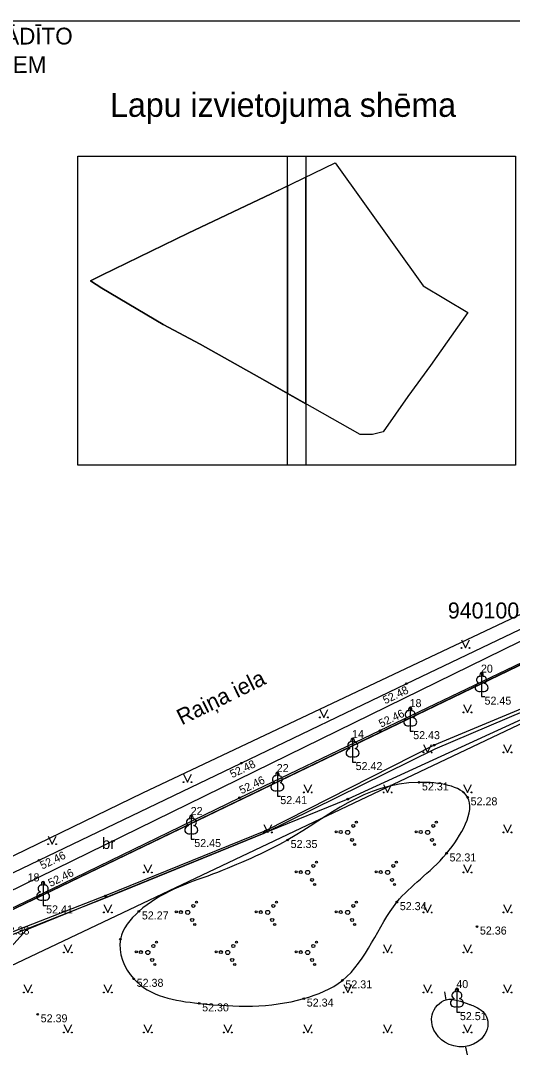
# Model space of a CAD drawing. Extents: x 619806 to 620082, y 405176 to 405386.
# Drawn here: x 619867.1 to 619897.8, y 405308.1 to 405373.2 of the extents above; entities that cross this region are included whole.
import ezdxf

# ---------------------------------------------------------------- set-up
doc = ezdxf.new("R2010")
doc.units = 0
for name, color, linetype in [('24', 7, 'Continuous'), ('APGR_SARK_####_####_#', 7, 'Continuous'), ('APGS_VADP_ZSPR_####_#', 7, 'Continuous'), ('CELI_CMAL_####_####_#', 7, 'Continuous'), ('CELI_CSEG_####_TKST_#', 7, 'Continuous'), ('CELI_IELA_####_TKST_#', 7, 'Continuous'), ('RAMI_PLAN_####_TKST_#', 7, 'Continuous'), ('RAMI_UZMR_####_####_#', 7, 'Continuous'), ('RELJ_AATZ_####_TKST_#', 7, 'Continuous'), ('RELJ_ELEM_####_####_#', 7, 'Continuous'), ('RELJ_HORZ_PAMT_####_#', 7, 'Continuous'), ('ROBZ_PROJ_####_TKST_#', 7, 'Continuous'), ('ROBZ_UZMR_####_####_#', 7, 'Continuous'), ('SAKT_VADP_KABE_####_#', 7, 'Continuous'), ('TERT_DIAM_####_TKST_#', 7, 'Continuous'), ('TERT_ELEM_####_####_#', 7, 'Continuous'), ('TERT_KONT_####_####_#', 7, 'Continuous')]:
    doc.layers.add(name, color=color, linetype=linetype)

msp = doc.modelspace()

# ---------------------------------------------------------------- linework, layer by layer
at = {"layer": '24'}
msp.add_line((619931.837, 405349.12), (619818.193, 405294.391), dxfattribs=at)
at = {"layer": 'APGR_SARK_####_####_#'}
msp.add_lwpolyline([(619818.56, 405291.467), (619964.609, 405360.731), (619976.198, 405343.424)], dxfattribs=at)
at = {"layer": 'APGS_VADP_ZSPR_####_#'}
for points in [[(619961.504, 405361.726), (619961.549, 405360.889), (619955.561, 405357.47), (619948.629, 405353.911), (619942.586, 405351.309), (619934.737, 405347.784), (619926.308, 405343.807), (619921.62, 405341.722), (619914.616, 405338.589), (619904.064, 405332.419), (619892.947, 405327.707), (619882.253, 405322.432), (619872.343, 405318.394), (619866.043, 405315.914), (619858.147, 405313.031), (619849.141, 405308.474), (619837.591, 405302.476), (619829.867, 405298.738), (619827.533, 405297.619), (619826.332, 405294.789), (619825.868, 405290.973), (619826.009, 405290.873), (619827.279, 405290.766)], [(619961.504, 405361.726), (619961.582, 405360.944), (619961.547, 405359.255), (619942.312, 405349.715), (619925.4, 405342.794), (619907.997, 405333.971), (619887.51, 405324.581), (619867.415, 405316.417), (619859.827, 405308.06), (619845.28, 405301.51), (619837.164, 405301.798), (619827.1, 405298.963), (619826.475, 405294.709), (619826.025, 405290.988), (619827.279, 405290.766)], [(619904.019, 405332.565), (619892.911, 405327.951), (619882.359, 405322.589), (619872.341, 405318.531), (619866.186, 405316.142), (619865.74, 405316.62), (619866.013, 405316.067), (619858.137, 405313.192), (619849.107, 405308.602), (619837.621, 405302.637), (619837.373, 405303.082), (619837.457, 405302.572), (619827.49, 405297.724), (619826.22, 405294.811), (619826.787, 405293.322), (619828.348, 405292.084), (619828.449, 405291.159), (619827.279, 405290.766)]]:
    msp.add_lwpolyline(points, dxfattribs=at)
at = {"layer": 'CELI_CMAL_####_####_#'}
for points in [[(619825.042, 405301.626), (619825.997, 405300.736), (619826.865, 405300.888), (619837.411, 405305.982), (619845.924, 405310.094), (619856.691, 405315.252), (619868.203, 405320.761), (619880.848, 405326.828), (619891.162, 405331.79), (619903.487, 405337.685), (619914.792, 405343.079), (619924.282, 405347.611), (619934.782, 405352.643), (619943.391, 405356.735), (619942.998, 405357.499)], [(619901.141, 405301.297), (619895.285, 405291.495), (619886.767, 405291.266), (619876.357, 405290.867), (619868.929, 405290.713), (619868.879, 405291.869), (619865.764, 405291.699), (619865.807, 405290.556), (619863.458, 405290.505), (619853.554, 405290.137), (619841.43, 405289.76), (619840.169, 405289.507), (619836.17, 405288.32), (619833.502, 405287.788), (619826.905, 405297.999), (619827.372, 405299.068), (619837.906, 405304.107), (619846.534, 405308.229), (619856.914, 405313.201), (619868.255, 405318.592), (619880.738, 405324.67), (619889.516, 405328.858), (619904.867, 405336.211)]]:
    msp.add_lwpolyline(points, dxfattribs=at)
at = {"layer": 'RAMI_PLAN_####_TKST_#'}
for p, q in [((619883.741, 405362.889), (619882.724, 405362.393)), ((619884.891, 405363.451), (619883.741, 405362.889)), ((619883.741, 405349.933), (619883.741, 405362.889)), ((619883.741, 405362.889), (619883.741, 405349.933)), ((619884.891, 405349.28), (619884.891, 405363.451)), ((619883.741, 405349.933), (619884.891, 405349.28))]:
    msp.add_line(p, q, dxfattribs=at)
for points in [[(619805.793, 405180.095), (619805.793, 405373.209), (619948.393, 405373.209), (619948.393, 405180.095)], [(619870.631, 405345.448), (619870.631, 405364.759), (619884.891, 405364.759), (619884.891, 405345.448)], [(619877.521, 405359.936), (619882.724, 405362.393), (619886.719, 405364.343), (619892.226, 405356.641), (619895.022, 405354.986), (619892.671, 405351.667), (619891.267, 405349.73), (619889.712, 405347.531), (619889.052, 405347.356), (619888.285, 405347.354), (619882.319, 405350.74), (619878.266, 405353.014), (619875.96, 405354.244), (619872.117, 405356.51), (619871.426, 405356.959), (619872.117, 405357.314)], [(619883.741, 405345.448), (619883.741, 405364.759), (619898.001, 405364.759), (619898.001, 405345.448)]]:
    msp.add_lwpolyline(points, close=True, dxfattribs=at)
msp.add_lwpolyline([(619882.724, 405362.393), (619877.521, 405359.936), (619872.117, 405357.314), (619871.426, 405356.959), (619872.117, 405356.51), (619875.96, 405354.244), (619878.266, 405353.014), (619882.319, 405350.74), (619883.741, 405349.933)], dxfattribs=at)
at = {"layer": 'RAMI_UZMR_####_####_#'}
msp.add_lwpolyline([(619874.687, 405324.979), (619926.719, 405349.544), (619966.669, 405369.042), (620021.738, 405292.03), (620049.703, 405275.476), (620026.189, 405242.287), (620012.147, 405222.917), (619996.603, 405200.928), (619989.997, 405199.173), (619982.328, 405199.155), (619922.669, 405233.014), (619882.137, 405255.756), (619859.084, 405268.056), (619820.646, 405290.715), (619813.744, 405295.206), (619820.645, 405298.752)], close=True, dxfattribs=at)
at = {"layer": 'RELJ_ELEM_####_####_#'}
for centre in [(619891.162, 405331.79), (619889.516, 405328.858), (619892.911, 405327.951), (619880.848, 405326.828), (619891.96, 405325.624), (619880.738, 405324.67), (619887.51, 405324.581), (619895.002, 405324.693), (619882.359, 405322.589), (619883.748, 405322.027), (619893.682, 405321.188), (619868.203, 405320.761), (619868.255, 405318.592), (619872.341, 405318.531), (619890.574, 405318.144), (619874.444, 405317.563), (619895.583, 405316.619), (619867.415, 405316.417), (619873.286, 405315.83), (619874.12, 405313.353), (619887.171, 405313.256), (619884.756, 405312.118), (619878.214, 405311.817), (619868.118, 405311.135)]:
    msp.add_circle(centre, 0.05, dxfattribs=at)
at = {"layer": 'RELJ_HORZ_PAMT_####_#'}
for p, q in [((619893.545, 405312.534), (619893.634, 405312.042)), ((619894.99, 405308.597), (619894.891, 405309.087))]:
    msp.add_line(p, q, dxfattribs=at)
msp.add_spline([(619895.163, 405311.743), (619895.492, 405311.611), (619896.23, 405310.859), (619895.861, 405309.606), (619893.569, 405309.395), (619892.779, 405311.096), (619893.662, 405312.046), (619895.081, 405311.766), (619895.161, 405311.743)], degree=3, dxfattribs=at)
at = {"layer": 'ROBZ_UZMR_####_####_#'}
msp.add_line((619818.193, 405294.391), (619931.837, 405349.12), dxfattribs=at)
at = {"layer": 'SAKT_VADP_KABE_####_#'}
msp.add_lwpolyline([(619816.151, 405294.73), (619838.42, 405305.23), (619866.149, 405318.697), (619899.278, 405334.929), (619937.202, 405353.635), (619962.924, 405366.289), (619964.424, 405369.208)], dxfattribs=at)
at = {"layer": 'TERT_ELEM_####_####_#'}
for p, q in [((619894.615, 405334.523), (619894.865, 405334.023)), ((619894.865, 405334.023), (619895.115, 405334.523)), ((619895.873, 405331.33), (619895.873, 405330.983)), ((619895.873, 405330.983), (619896.073, 405330.983)), ((619894.75, 405330.5), (619895, 405330)), ((619895, 405330), (619895.25, 405330.5)), ((619885.766, 405330.188), (619886.016, 405329.688)), ((619886.016, 405329.688), (619886.266, 405330.188)), ((619891.41, 405329.174), (619891.41, 405328.827)), ((619891.41, 405328.827), (619891.61, 405328.827)), ((619892.25, 405328), (619892.5, 405327.5)), ((619892.5, 405327.5), (619892.75, 405328)), ((619897.25, 405328), (619897.5, 405327.5)), ((619897.5, 405327.5), (619897.75, 405328)), ((619887.811, 405327.242), (619887.811, 405326.895)), ((619887.811, 405326.895), (619888.011, 405326.895)), ((619877.237, 405326.142), (619877.487, 405325.642)), ((619877.487, 405325.642), (619877.737, 405326.142)), ((619883.103, 405325.116), (619883.103, 405324.769)), ((619884.75, 405325.5), (619885, 405325)), ((619885, 405325), (619885.25, 405325.5)), ((619889.75, 405325.5), (619890, 405325)), ((619890, 405325), (619890.25, 405325.5)), ((619894.75, 405325.5), (619895, 405325)), ((619895, 405325), (619895.25, 405325.5)), ((619883.103, 405324.769), (619883.303, 405324.769)), ((619882.25, 405323), (619882.5, 405322.5)), ((619882.5, 405322.5), (619882.75, 405323)), ((619897.25, 405323), (619897.5, 405322.5)), ((619897.5, 405322.5), (619897.75, 405323)), ((619868.771, 405322.264), (619869.021, 405321.764)), ((619869.021, 405321.764), (619869.271, 405322.264)), ((619877.722, 405322.433), (619877.722, 405322.086)), ((619877.722, 405322.086), (619877.922, 405322.086)), ((619874.75, 405320.5), (619875, 405320)), ((619875, 405320), (619875.25, 405320.5)), ((619894.75, 405320.5), (619895, 405320)), ((619895, 405320), (619895.25, 405320.5)), ((619868.456, 405318.287), (619868.456, 405317.94)), ((619868.456, 405317.94), (619868.656, 405317.94)), ((619872.25, 405318), (619872.5, 405317.5)), ((619872.5, 405317.5), (619872.75, 405318)), ((619892.25, 405318), (619892.5, 405317.5)), ((619892.5, 405317.5), (619892.75, 405318)), ((619897.25, 405318), (619897.5, 405317.5)), ((619897.5, 405317.5), (619897.75, 405318)), ((619869.75, 405315.5), (619870, 405315)), ((619870, 405315), (619870.25, 405315.5)), ((619889.75, 405315.5), (619890, 405315)), ((619890, 405315), (619890.25, 405315.5)), ((619894.75, 405315.5), (619895, 405315)), ((619895, 405315), (619895.25, 405315.5)), ((619867.25, 405313), (619867.5, 405312.5)), ((619867.5, 405312.5), (619867.75, 405313)), ((619872.25, 405313), (619872.5, 405312.5)), ((619872.5, 405312.5), (619872.75, 405313)), ((619887.25, 405313), (619887.5, 405312.5)), ((619887.5, 405312.5), (619887.75, 405313)), ((619892.25, 405313), (619892.5, 405312.5)), ((619892.5, 405312.5), (619892.75, 405313)), ((619897.25, 405313), (619897.5, 405312.5)), ((619897.5, 405312.5), (619897.75, 405313)), ((619894.333, 405311.619), (619894.333, 405311.272)), ((619894.333, 405311.272), (619894.533, 405311.272)), ((619869.75, 405310.5), (619870, 405310)), ((619870, 405310), (619870.25, 405310.5)), ((619874.75, 405310.5), (619875, 405310)), ((619875, 405310), (619875.25, 405310.5)), ((619879.75, 405310.5), (619880, 405310)), ((619880, 405310), (619880.25, 405310.5)), ((619884.75, 405310.5), (619885, 405310)), ((619885, 405310), (619885.25, 405310.5)), ((619889.75, 405310.5), (619890, 405310)), ((619890, 405310), (619890.25, 405310.5)), ((619894.75, 405310.5), (619895, 405310)), ((619895, 405310), (619895.25, 405310.5))]:
    msp.add_line(p, q, dxfattribs=at)
for points in [[(619895.873, 405332.483), (619895.873, 405331.33)], [(619895.963, 405332.251), (619895.962, 405332.252)], [(619891.41, 405330.327), (619891.41, 405329.174)], [(619891.5, 405330.095), (619891.499, 405330.096)], [(619887.811, 405328.395), (619887.811, 405327.242)], [(619887.901, 405328.163), (619887.9, 405328.164)], [(619883.103, 405326.269), (619883.103, 405325.116)], [(619883.193, 405326.037), (619883.192, 405326.038)], [(619877.722, 405323.586), (619877.722, 405322.433)], [(619877.812, 405323.354), (619877.811, 405323.355)], [(619868.456, 405319.44), (619868.456, 405318.287)], [(619868.546, 405319.208), (619868.545, 405319.209)], [(619894.333, 405312.772), (619894.333, 405311.619)], [(619894.423, 405312.54), (619894.422, 405312.541)]]:
    msp.add_lwpolyline(points, dxfattribs=at)
for centre, radius in [((619894.615, 405334.023), 0.028), ((619895.115, 405334.023), 0.0263), ((619885.765, 405329.688), 0.028), ((619886.265, 405329.688), 0.0263), ((619894.75, 405330), 0.028), ((619895.25, 405330), 0.0263), ((619892.25, 405327.5), 0.028), ((619892.75, 405327.5), 0.0263), ((619897.25, 405327.5), 0.028), ((619897.75, 405327.5), 0.0263), ((619877.237, 405325.641), 0.028), ((619877.737, 405325.641), 0.0263), ((619884.75, 405325), 0.028), ((619885.25, 405325), 0.0263), ((619889.75, 405325), 0.028), ((619890.25, 405325), 0.0263), ((619894.75, 405325), 0.028), ((619895.25, 405325), 0.0263), ((619888.044, 405323.139), 0.064), ((619893.044, 405323.139), 0.064), ((619882.25, 405322.5), 0.028), ((619882.75, 405322.5), 0.0263), ((619886.782, 405322.534), 0.064), ((619887.066, 405322.521), 0.096), ((619887.5, 405322.5), 0.128), ((619887.848, 405322.908), 0.096), ((619891.782, 405322.534), 0.064), ((619892.066, 405322.521), 0.096), ((619892.5, 405322.5), 0.128), ((619892.848, 405322.908), 0.096), ((619897.25, 405322.5), 0.028), ((619897.75, 405322.5), 0.0263), ((619887.776, 405322.033), 0.096), ((619892.776, 405322.033), 0.096), ((619868.771, 405321.763), 0.028), ((619869.271, 405321.763), 0.0263), ((619887.934, 405321.744), 0.064), ((619892.934, 405321.744), 0.064), ((619885.544, 405320.639), 0.064), ((619890.544, 405320.639), 0.064), ((619874.75, 405320), 0.028), ((619875.25, 405320), 0.0263), ((619884.282, 405320.034), 0.064), ((619884.566, 405320.021), 0.096), ((619885, 405320), 0.128), ((619885.348, 405320.408), 0.096), ((619889.282, 405320.034), 0.064), ((619889.566, 405320.021), 0.096), ((619890, 405320), 0.128), ((619890.348, 405320.408), 0.096), ((619894.75, 405320), 0.028), ((619895.25, 405320), 0.0263), ((619885.276, 405319.533), 0.096), ((619885.434, 405319.244), 0.064), ((619890.276, 405319.533), 0.096), ((619890.434, 405319.244), 0.064), ((619877.848, 405317.908), 0.096), ((619878.044, 405318.139), 0.064), ((619882.848, 405317.908), 0.096), ((619883.044, 405318.139), 0.064), ((619887.848, 405317.908), 0.096), ((619888.044, 405318.139), 0.064), ((619872.25, 405317.5), 0.028), ((619872.75, 405317.5), 0.0263), ((619876.782, 405317.534), 0.064), ((619877.066, 405317.521), 0.096), ((619877.5, 405317.5), 0.128), ((619881.782, 405317.534), 0.064), ((619882.066, 405317.521), 0.096), ((619882.5, 405317.5), 0.128), ((619886.782, 405317.534), 0.064), ((619887.066, 405317.521), 0.096), ((619887.5, 405317.5), 0.128), ((619892.25, 405317.5), 0.028), ((619892.75, 405317.5), 0.0263), ((619897.25, 405317.5), 0.028), ((619897.75, 405317.5), 0.0263), ((619877.776, 405317.033), 0.096), ((619877.934, 405316.744), 0.064), ((619882.776, 405317.033), 0.096), ((619882.934, 405316.744), 0.064), ((619887.776, 405317.033), 0.096), ((619887.934, 405316.744), 0.064), ((619875.348, 405315.408), 0.096), ((619875.544, 405315.639), 0.064), ((619880.348, 405315.408), 0.096), ((619880.544, 405315.639), 0.064), ((619885.348, 405315.408), 0.096), ((619885.544, 405315.639), 0.064), ((619869.75, 405315), 0.028), ((619870.25, 405315), 0.0263), ((619874.282, 405315.034), 0.064), ((619874.566, 405315.021), 0.096), ((619875, 405315), 0.128), ((619879.282, 405315.034), 0.064), ((619879.566, 405315.021), 0.096), ((619880, 405315), 0.128), ((619884.282, 405315.034), 0.064), ((619884.566, 405315.021), 0.096), ((619885, 405315), 0.128), ((619889.75, 405315), 0.028), ((619890.25, 405315), 0.0263), ((619894.75, 405315), 0.028), ((619895.25, 405315), 0.0263), ((619875.276, 405314.533), 0.096), ((619875.434, 405314.244), 0.064), ((619880.276, 405314.533), 0.096), ((619880.434, 405314.244), 0.064), ((619885.276, 405314.533), 0.096), ((619885.434, 405314.244), 0.064), ((619867.25, 405312.5), 0.028), ((619867.75, 405312.5), 0.0263), ((619872.25, 405312.5), 0.028), ((619872.75, 405312.5), 0.0263), ((619887.25, 405312.5), 0.028), ((619887.75, 405312.5), 0.0263), ((619892.25, 405312.5), 0.028), ((619892.75, 405312.5), 0.0263), ((619897.25, 405312.5), 0.028), ((619897.75, 405312.5), 0.0263), ((619869.75, 405310), 0.028), ((619870.25, 405310), 0.0263), ((619874.75, 405310), 0.028), ((619875.25, 405310), 0.0263), ((619879.75, 405310), 0.028), ((619880.25, 405310), 0.0263), ((619884.75, 405310), 0.028), ((619885.25, 405310), 0.0263), ((619889.75, 405310), 0.028), ((619890.25, 405310), 0.0263), ((619894.75, 405310), 0.028), ((619895.25, 405310), 0.0263)]:
    msp.add_circle(centre, radius, dxfattribs=at)
for centre, major_axis, ratio, start_param, end_param in [((619895.745, 405332.038), (-0.039, -0.212), 0.861323, 3.141593, 6.283185), ((619895.873, 405332.333), (0, -0.15), 0.707107, 3.14537, 5.287485), ((619895.873, 405332.333), (0, -0.15), 0.707107, 0.995701, 3.137816), ((619896.001, 405332.038), (0.039, -0.212), 0.861323, 0, 3.141593), ((619895.783, 405331.576), (0.307, 0.095), 0.814445, 1.570796, 4.752015), ((619895.963, 405331.576), (-0.307, 0.095), 0.814445, 1.531171, 4.712389), ((619891.41, 405330.177), (0, -0.15), 0.707107, 3.14537, 5.287485), ((619891.41, 405330.177), (0, -0.15), 0.707107, 0.995701, 3.137816), ((619891.32, 405329.42), (0.307, 0.095), 0.814445, 1.570796, 4.752015), ((619891.282, 405329.882), (-0.039, -0.212), 0.861323, 3.141593, 6.283185), ((619891.5, 405329.42), (-0.307, 0.095), 0.814445, 1.531171, 4.712389), ((619891.538, 405329.882), (0.039, -0.212), 0.861323, 0, 3.141593), ((619887.811, 405328.245), (0, -0.15), 0.707107, 3.14537, 5.287485), ((619887.811, 405328.245), (0, -0.15), 0.707107, 0.995701, 3.137816), ((619887.721, 405327.488), (0.307, 0.095), 0.814445, 1.570796, 4.752015), ((619887.683, 405327.95), (-0.039, -0.212), 0.861323, 3.141593, 6.283185), ((619887.901, 405327.488), (-0.307, 0.095), 0.814445, 1.531171, 4.712389), ((619887.939, 405327.95), (0.039, -0.212), 0.861323, 0, 3.141593), ((619882.975, 405325.824), (-0.039, -0.212), 0.861323, 3.141593, 6.283185), ((619883.103, 405326.119), (0, -0.15), 0.707107, 3.14537, 5.287485), ((619883.103, 405326.119), (0, -0.15), 0.707107, 0.995701, 3.137816), ((619883.231, 405325.824), (0.039, -0.212), 0.861323, 0, 3.141593), ((619883.013, 405325.362), (0.307, 0.095), 0.814445, 1.570796, 4.752015), ((619883.193, 405325.362), (-0.307, 0.095), 0.814445, 1.531171, 4.712389), ((619877.594, 405323.141), (-0.039, -0.212), 0.861323, 3.141593, 6.283185), ((619877.722, 405323.436), (0, -0.15), 0.707107, 3.14537, 5.287485), ((619877.722, 405323.436), (0, -0.15), 0.707107, 0.995701, 3.137816), ((619877.85, 405323.141), (0.039, -0.212), 0.861323, 0, 3.141593), ((619877.632, 405322.679), (0.307, 0.095), 0.814445, 1.570796, 4.752015), ((619877.812, 405322.679), (-0.307, 0.095), 0.814445, 1.531171, 4.712389), ((619868.328, 405318.995), (-0.039, -0.212), 0.861323, 3.141593, 6.283185), ((619868.456, 405319.29), (0, -0.15), 0.707107, 3.14537, 5.287485), ((619868.456, 405319.29), (0, -0.15), 0.707107, 0.995701, 3.137816), ((619868.584, 405318.995), (0.039, -0.212), 0.861323, 0, 3.141593), ((619868.366, 405318.533), (0.307, 0.095), 0.814445, 1.570796, 4.752015), ((619868.546, 405318.533), (-0.307, 0.095), 0.814445, 1.531171, 4.712389), ((619894.333, 405312.622), (0, -0.15), 0.707107, 3.14537, 5.287485), ((619894.333, 405312.622), (0, -0.15), 0.707107, 0.995701, 3.137816), ((619894.243, 405311.865), (0.307, 0.095), 0.814445, 1.570796, 4.752015), ((619894.205, 405312.327), (-0.039, -0.212), 0.861323, 3.141593, 6.283185), ((619894.423, 405311.865), (-0.307, 0.095), 0.814445, 1.531171, 4.712389), ((619894.461, 405312.327), (0.039, -0.212), 0.861323, 0, 3.141593)]:
    msp.add_ellipse(centre, major_axis=major_axis, ratio=ratio, start_param=start_param, end_param=end_param, dxfattribs=at)
at = {"layer": 'TERT_KONT_####_####_#'}
msp.add_spline([(619879.054, 405319.881), (619883.748, 405322.027), (619891.96, 405325.624), (619895.002, 405324.693), (619893.682, 405321.188), (619890.574, 405318.144), (619887.171, 405313.256), (619884.756, 405312.118), (619878.214, 405311.817), (619874.12, 405313.353), (619873.286, 405315.83), (619874.444, 405317.563), (619879.054, 405319.881)], degree=3, dxfattribs=at)

# ---------------------------------------------------------------- texts
at = {"layer": 'CELI_CSEG_####_TKST_#'}
msp.add_text('br', height=0.7, dxfattribs=at).set_placement((619872.134, 405321.466))
at = {"layer": 'CELI_IELA_####_TKST_#'}
msp.add_text('Raiņa iela', height=1, rotation=26.17168, dxfattribs=at).set_placement((619877.123, 405329.179))
at = {"layer": 'RAMI_PLAN_####_TKST_#'}
for s, height, rotation, p in [('VALKAS PILSĒTAS EKSPLUATĒJOŠO ORGANIZĀCIJU APLIECINĀJUMS PAR PLĀNĀ UZRĀDĪTO', 1.04756, 0.06657, (619807.173, 405371.66)), (' APAKŠZEMES  KOMUNIKĀCIJU ATBILSTĪBU ŠO ORGANIZĀCIJU ARHĪVU MATERIĀLIEM', 1.04756, 0.06657, (619810.206, 405369.882)), ('Lapu izvietojuma shēma', 1.5, 360, (619872.646, 405367.21))]:
    msp.add_text(s, height=height, rotation=rotation, dxfattribs=at).set_placement(p)
at = {"layer": 'RELJ_AATZ_####_TKST_#'}
for s, rotation, p in [(' 52.48', 25.56161, (619889.677, 405330.423)), (' 52.46', 25.59403, (619889.423, 405328.962)), (' 52.48', 25.69191, (619880.115, 405325.802)), (' 52.46', 25.5059, (619880.696, 405324.801)), (' 52.46', 25.63143, (619868.243, 405320.096)), (' 52.46', 25.96155, (619868.754, 405319.005))]:
    msp.add_text(s, height=0.5, rotation=rotation, dxfattribs=at).set_placement(p)
for s, p in [(' 52.45', (619895.873, 405330.483)), (' 52.43', (619891.41, 405328.327)), (' 52.42', (619887.811, 405326.395)), (' 52.31', (619891.96, 405325.124)), (' 52.41', (619883.103, 405324.269)), (' 52.28', (619895.002, 405324.193)), (' 52.45', (619877.722, 405321.586)), (' 52.35', (619883.748, 405321.527)), (' 52.31', (619893.682, 405320.688)), (' 52.41', (619868.456, 405317.44)), (' 52.34', (619890.574, 405317.644)), (' 52.27', (619874.444, 405317.063)), (' 52.38', (619865.74, 405316.12)), (' 52.36', (619895.583, 405316.119)), (' 52.38', (619874.12, 405312.853)), (' 52.31', (619887.171, 405312.756)), (' 52.34', (619884.756, 405311.618)), (' 52.30', (619878.214, 405311.317)), (' 52.39', (619868.118, 405310.635)), (' 52.51', (619894.333, 405310.772))]:
    msp.add_text(s, height=0.5, dxfattribs=at).set_placement(p)
at = {"layer": 'ROBZ_PROJ_####_TKST_#'}
msp.add_text('94010010536', height=1, dxfattribs=at).set_placement((619893.763, 405335.866))
at = {"layer": 'TERT_DIAM_####_TKST_#'}
for s, p in [(' 20', (619895.648, 405332.483)), (' 18', (619891.185, 405330.327)), (' 14', (619887.586, 405328.395)), (' 22', (619882.878, 405326.269)), (' 22', (619877.497, 405323.586)), (' 18', (619867.296, 405319.44)), (' 40', (619894.108, 405312.772))]:
    msp.add_text(s, height=0.5, dxfattribs=at).set_placement(p)

doc.saveas('drawing.dxf')
